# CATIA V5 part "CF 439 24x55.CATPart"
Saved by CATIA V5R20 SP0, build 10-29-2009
Part number: CF 439 24x55
Definition: NONE
Nomenclature: CF 439 24x55
Source: Unknown
Description: CF 439 24x55
Bounding box of the stored display mesh (mm): x -22 to 22, y 0 to 55, z -22 to 22
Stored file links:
  C:\Users\Utente\Desktop\IO LAVORO\3D X SITO CF\X SITO\CF 439\CF 439 24x55.CATPart
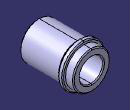
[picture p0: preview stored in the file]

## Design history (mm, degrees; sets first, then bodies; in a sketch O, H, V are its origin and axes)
Body1 "CF 439 24x55" (main body)
  Solid1: solid without history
